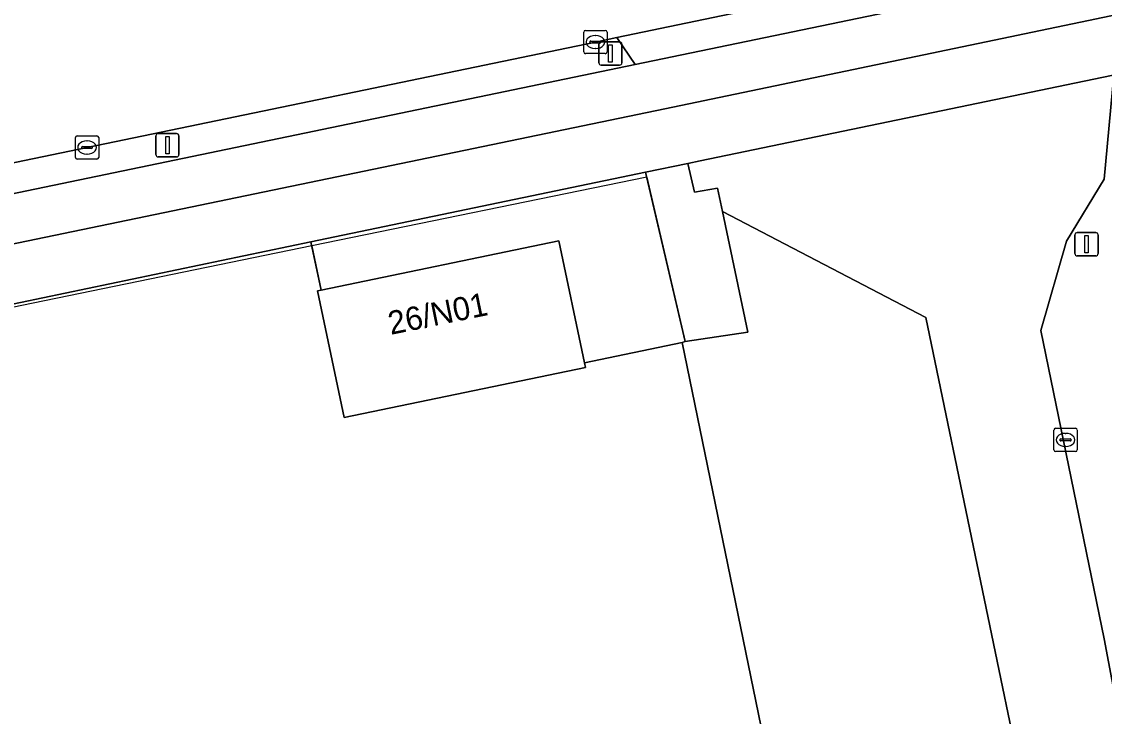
# Model space of a CAD drawing. Extents: x 164494 to 166241, y 382475 to 384495.
# Drawn here: x 164884.73 to 164931.19, y 384302.19 to 384331.99 of the extents above; entities that cross this region are included whole.
import ezdxf

# ---------------------------------------------------------------- set-up
doc = ezdxf.new("R2010")
doc.units = 0
for name, color, linetype in [('IMGEO_Berm_groen', 7, 'Continuous'), ('IMGEO_Erf', 7, 'Continuous'), ('IMGEO_Fietspad_open', 7, 'Continuous'), ('IMGEO_Groenvoorziening', 7, 'Continuous'), ('IMGEO_Hek', 7, 'Continuous'), ('IMGEO_Kolk', 7, 'Continuous'), ('IMGEO_Lichtmast', 7, 'Continuous'), ('IMGEO_Pand', 7, 'Continuous'), ('IMGEO_Pand_nummerreeks', 7, 'Continuous'), ('IMGEO_Rijbaan_lokaal_open', 7, 'Continuous'), ('IMGEO_Voetpad_open', 7, 'Continuous')]:
    doc.layers.add(name, color=color, linetype=linetype)

msp = doc.modelspace()

# ---------------------------------------------------------------- linework, layer by layer
at = {"layer": 'IMGEO_Berm_groen'}
msp.add_lwpolyline([(164911.059, 384330.145), (164910.275, 384331.309), (164909.353, 384331.116), (164887.539, 384326.59), (164866.083, 384322.138), (164847.04, 384318.189), (164832.428, 384315.154), (164832.678, 384313.85), (164868.55, 384321.331)], close=True, dxfattribs=at)
at = {"layer": 'IMGEO_Erf'}
msp.add_lwpolyline([(164931.595, 384329.704), (164931.189, 384325.235), (164929.571, 384322.569), (164928.461, 384318.744), (164931.192, 384305.516), (164935.029, 384285.096), (164930.87, 384284.21), (164924.878, 384283.015), (164922.096, 384296.28), (164917.769, 384295.38), (164913.081, 384318.227), (164908.88, 384317.354), (164908.923, 384317.148), (164898.571, 384315.011), (164897.432, 384320.445), (164897.584, 384320.476), (164897.149, 384322.536), (164869.34, 384316.739), (164837.573, 384310.195), (164815.303, 384305.586), (164810.439, 384304.577), (164802.345, 384302.907), (164801.347, 384302.69), (164878.385, 384108.38)], dxfattribs=at)
at = {"layer": 'IMGEO_Fietspad_open'}
for points in [[(165118.509, 384373.384), (165114.768, 384372.637), (165100.699, 384369.712), (165051.79, 384359.513), (165001.461, 384348.974), (164996.183, 384347.859), (164980.371, 384344.544), (164956.926, 384339.68), (164933.359, 384334.783), (164911.059, 384330.145), (164868.55, 384321.331), (164832.678, 384313.85), (164825.97, 384312.501), (164814.364, 384310.101), (164814.35, 384310.172), (164809.331, 384309.126), (164809.333, 384309.08), (164801.696, 384307.495)], [(164802.068, 384305.407), (164809.925, 384307.04), (164833.08, 384311.822), (164838.611, 384312.969), (164868.92, 384319.253), (164912.329, 384328.255), (164932.507, 384332.46), (164958.923, 384337.938), (164978.743, 384342.085), (164996.584, 384345.814), (165001.876, 384346.919), (165052.181, 384357.436), (165101.155, 384367.679), (165118.614, 384371.278), (165123.59, 384372.323)]]:
    msp.add_lwpolyline(points, dxfattribs=at)
at = {"layer": 'IMGEO_Groenvoorziening'}
msp.add_lwpolyline([(164930.735, 384284.803), (164925.86, 384283.826), (164923.229, 384296.371), (164928.077, 384297.39), (164923.539, 384319.297), (164914.805, 384323.848), (164915.899, 384318.672), (164913.199, 384318.262), (164913.081, 384318.227), (164917.769, 384295.38), (164922.096, 384296.28), (164924.878, 384283.015), (164930.87, 384284.21)], close=True, dxfattribs=at)
at = {"layer": 'IMGEO_Hek'}
for points in [[(164911.555, 384325.324), (164897.184, 384322.369)], [(164911.555, 384325.324), (164913.199, 384318.262)], [(164897.184, 384322.369), (164884.739, 384319.811), (164842.119, 384310.96), (164840.566, 384310.552)], [(164897.184, 384322.369), (164897.584, 384320.476)], [(164913.081, 384318.227), (164908.88, 384317.354)], [(164913.199, 384318.262), (164913.081, 384318.227)], [(164913.081, 384318.227), (164917.769, 384295.38)]]:
    msp.add_lwpolyline(points, dxfattribs=at)
at = {"layer": 'IMGEO_Kolk'}
for p, q in [((164908.852, 384330.69), (164908.852, 384331.542)), ((164908.927, 384331.616), (164909.779, 384331.616)), ((164909.34, 384331.396), (164909.365, 384331.396)), ((164909.853, 384331.542), (164909.853, 384330.69)), ((164909.111, 384331.11), (164909.111, 384331.122)), ((164909.549, 384331.073), (164909.151, 384331.073)), ((164909.154, 384331.159), (164909.552, 384331.159)), ((164909.595, 384331.122), (164909.595, 384331.11)), ((164909.779, 384330.616), (164908.927, 384330.616)), ((164909.363, 384330.836), (164909.338, 384330.836)), ((164887.038, 384326.164), (164887.038, 384327.016)), ((164887.113, 384327.09), (164887.965, 384327.09)), ((164887.526, 384326.87), (164887.551, 384326.87)), ((164888.039, 384327.016), (164888.039, 384326.164)), ((164887.297, 384326.584), (164887.297, 384326.596)), ((164887.735, 384326.547), (164887.337, 384326.547)), ((164887.34, 384326.633), (164887.738, 384326.633)), ((164887.549, 384326.31), (164887.524, 384326.31)), ((164887.781, 384326.596), (164887.781, 384326.584)), ((164887.965, 384326.09), (164887.113, 384326.09)), ((164929.029, 384313.618), (164929.029, 384314.47)), ((164929.104, 384314.544), (164929.956, 384314.544)), ((164929.517, 384314.324), (164929.542, 384314.324)), ((164930.03, 384314.47), (164930.03, 384313.618)), ((164929.288, 384314.038), (164929.288, 384314.05)), ((164929.726, 384314.001), (164929.328, 384314.001)), ((164929.331, 384314.087), (164929.729, 384314.087)), ((164929.54, 384313.764), (164929.515, 384313.764)), ((164929.772, 384314.05), (164929.772, 384314.038)), ((164929.956, 384313.544), (164929.104, 384313.544))]:
    msp.add_line(p, q, dxfattribs=at)
for points in [[(164908.852, 384330.69), (164908.852, 384331.542)], [(164908.927, 384331.616), (164909.779, 384331.616)], [(164909.853, 384331.542), (164909.853, 384330.69)], [(164909.779, 384330.616), (164908.927, 384330.616)], [(164887.038, 384326.164), (164887.038, 384327.016)], [(164887.113, 384327.09), (164887.965, 384327.09)], [(164888.039, 384327.016), (164888.039, 384326.164)], [(164887.965, 384326.09), (164887.113, 384326.09)], [(164929.029, 384313.618), (164929.029, 384314.47)], [(164929.104, 384314.544), (164929.956, 384314.544)], [(164930.03, 384314.47), (164930.03, 384313.618)], [(164929.956, 384313.544), (164929.104, 384313.544)]]:
    msp.add_lwpolyline(points, dxfattribs=at)
for centre, radius, start, end in [((164908.929, 384331.54), 0.0765, 91.552, 178.448), ((164908.929, 384331.54), 0.0765, 91.552, 178.448), ((164909.777, 384331.54), 0.0765, 1.552, 88.448), ((164909.777, 384331.54), 0.0765, 1.552, 88.448), ((164909.151, 384331.119), 0.0403, 85.8775, 175.7526), ((164909.148, 384331.109), 0.0366, 178.938, 274.7102), ((164909.552, 384331.116), 0.043, 264.8664, 352.4533), ((164909.556, 384331.121), 0.0386, 1.7309, 96.639), ((164908.929, 384330.692), 0.0765, 181.552, 268.448), ((164908.929, 384330.692), 0.0765, 181.552, 268.448), ((164909.777, 384330.692), 0.0765, 271.552, 358.448), ((164909.777, 384330.692), 0.0765, 271.552, 358.448), ((164887.115, 384327.014), 0.0765, 91.552, 178.448), ((164887.115, 384327.014), 0.0765, 91.552, 178.448), ((164887.963, 384327.014), 0.0765, 1.552, 88.448), ((164887.963, 384327.014), 0.0765, 1.552, 88.448), ((164887.337, 384326.593), 0.0403, 85.8775, 175.7526), ((164887.334, 384326.583), 0.0366, 178.938, 274.7102), ((164887.738, 384326.59), 0.043, 264.8664, 352.4533), ((164887.742, 384326.595), 0.0386, 1.7309, 96.639), ((164887.115, 384326.166), 0.0765, 181.552, 268.448), ((164887.115, 384326.166), 0.0765, 181.552, 268.448), ((164887.963, 384326.166), 0.0765, 271.552, 358.448), ((164887.963, 384326.166), 0.0765, 271.552, 358.448), ((164929.106, 384314.468), 0.0765, 91.552, 178.448), ((164929.106, 384314.468), 0.0765, 91.552, 178.448), ((164929.954, 384314.468), 0.0765, 1.552, 88.448), ((164929.954, 384314.468), 0.0765, 1.552, 88.448), ((164929.328, 384314.047), 0.0403, 85.8775, 175.7526), ((164929.325, 384314.037), 0.0366, 178.938, 274.7102), ((164929.729, 384314.044), 0.043, 264.8664, 352.4533), ((164929.733, 384314.049), 0.0386, 1.7309, 96.639), ((164929.106, 384313.62), 0.0765, 181.552, 268.448), ((164929.106, 384313.62), 0.0765, 181.552, 268.448), ((164929.954, 384313.62), 0.0765, 271.552, 358.448), ((164929.954, 384313.62), 0.0765, 271.552, 358.448)]:
    msp.add_arc(centre, radius, start, end, dxfattribs=at)
for centre, major_axis, ratio, start_param, end_param in [((164909.339, 384331.116), (-0.387, 0.002), 0.722429, 4.712389, 7.853982), ((164909.364, 384331.116), (-0.39, 0.002), 0.717154, 1.570796, 4.712389), ((164887.525, 384326.59), (-0.387, 0.002), 0.722429, 4.712389, 7.853982), ((164887.55, 384326.59), (-0.39, 0.002), 0.717154, 1.570796, 4.712389), ((164929.516, 384314.044), (-0.387, 0.002), 0.722429, 4.712389, 7.853982), ((164929.541, 384314.044), (-0.39, 0.002), 0.717154, 1.570796, 4.712389)]:
    msp.add_ellipse(centre, major_axis=major_axis, ratio=ratio, start_param=start_param, end_param=end_param, dxfattribs=at)
at = {"layer": 'IMGEO_Lichtmast'}
for p, q in [((164909.503, 384330.224), (164909.503, 384331.024)), ((164909.503, 384331.024), (164909.503, 384330.224)), ((164909.603, 384331.124), (164910.393, 384331.124)), ((164910.393, 384331.124), (164909.603, 384331.124)), ((164910.493, 384331.024), (164910.493, 384330.224)), ((164910.493, 384330.224), (164910.493, 384331.024)), ((164910.393, 384330.124), (164909.603, 384330.124)), ((164909.603, 384330.124), (164910.393, 384330.124)), ((164890.595, 384327.187), (164891.385, 384327.187)), ((164891.385, 384327.187), (164890.595, 384327.187)), ((164890.495, 384326.287), (164890.495, 384327.087)), ((164890.495, 384327.087), (164890.495, 384326.287)), ((164891.485, 384327.087), (164891.485, 384326.287)), ((164891.485, 384326.287), (164891.485, 384327.087)), ((164891.385, 384326.187), (164890.595, 384326.187)), ((164890.595, 384326.187), (164891.385, 384326.187)), ((164929.933, 384322.04), (164929.933, 384322.84)), ((164929.933, 384322.84), (164929.933, 384322.04)), ((164930.033, 384322.94), (164930.823, 384322.94)), ((164930.823, 384322.94), (164930.033, 384322.94)), ((164930.923, 384322.84), (164930.923, 384322.04)), ((164930.923, 384322.04), (164930.923, 384322.84)), ((164930.823, 384321.94), (164930.033, 384321.94)), ((164930.033, 384321.94), (164930.823, 384321.94))]:
    msp.add_line(p, q, dxfattribs=at)
for points in [[(164909.923, 384330.999), (164910.073, 384330.999), (164910.073, 384330.249), (164909.923, 384330.249), (164909.923, 384330.999)], [(164890.915, 384327.062), (164891.065, 384327.062), (164891.065, 384326.312), (164890.915, 384326.312), (164890.915, 384327.062)], [(164930.353, 384322.815), (164930.503, 384322.815), (164930.503, 384322.065), (164930.353, 384322.065), (164930.353, 384322.815)]]:
    msp.add_lwpolyline(points, dxfattribs=at)
for centre, start, end in [((164909.603, 384331.024), 90, 180), ((164909.603, 384331.024), 90, 180), ((164910.393, 384331.024), 0, 90), ((164910.393, 384331.024), 360, 90), ((164909.603, 384330.224), 180, 270), ((164909.603, 384330.224), 180, 270), ((164910.393, 384330.224), 270, 0), ((164910.393, 384330.224), 270, 0), ((164890.595, 384327.087), 90, 180), ((164890.595, 384327.087), 90, 180), ((164891.385, 384327.087), 0, 90), ((164891.385, 384327.087), 360, 90), ((164890.595, 384326.287), 180, 270), ((164890.595, 384326.287), 180, 270), ((164891.385, 384326.287), 270, 0), ((164891.385, 384326.287), 270, 0), ((164930.033, 384322.84), 90, 180), ((164930.033, 384322.84), 90, 180), ((164930.823, 384322.84), 0, 90), ((164930.823, 384322.84), 360, 90), ((164930.033, 384322.04), 180, 270), ((164930.033, 384322.04), 180, 270), ((164930.823, 384322.04), 270, 0), ((164930.823, 384322.04), 270, 0)]:
    msp.add_arc(centre, 0.1, start, end, dxfattribs=at)
at = {"layer": 'IMGEO_Pand'}
msp.add_lwpolyline([(164907.784, 384322.582), (164897.584, 384320.476), (164897.432, 384320.445), (164898.571, 384315.011), (164908.923, 384317.148), (164908.88, 384317.354)], close=True, dxfattribs=at)
at = {"layer": 'IMGEO_Rijbaan_lokaal_open'}
msp.add_lwpolyline([(164799.153, 384308.224), (164802.045, 384308.824), (164809.079, 384310.283), (164814.127, 384311.33), (164814.848, 384311.48), (164825.542, 384313.724), (164825.715, 384313.76), (164832.428, 384315.154), (164847.04, 384318.189), (164866.083, 384322.138), (164887.539, 384326.59), (164909.353, 384331.116), (164910.275, 384331.309), (164923.017, 384333.971), (164933.937, 384336.234)], dxfattribs=at)
for points in [[(164933.359, 384334.783), (164933.937, 384336.234), (164923.017, 384333.971), (164910.275, 384331.309), (164911.059, 384330.145)], [(164928.461, 384318.744), (164929.571, 384322.569), (164931.189, 384325.235), (164931.595, 384329.704), (164931.494, 384329.683), (164913.849, 384326.017), (164913.321, 384325.907), (164913.602, 384324.675), (164914.593, 384324.849), (164914.805, 384323.848), (164923.539, 384319.297), (164928.077, 384297.39), (164930.735, 384284.803), (164930.87, 384284.21), (164935.029, 384285.096), (164931.192, 384305.516)]]:
    msp.add_lwpolyline(points, close=True, dxfattribs=at)
at = {"layer": 'IMGEO_Voetpad_open'}
for points in [[(165123.59, 384372.323), (165118.614, 384371.278), (165101.155, 384367.679), (165052.181, 384357.436), (165001.876, 384346.919), (164996.584, 384345.814), (164978.743, 384342.085), (164958.923, 384337.938), (164932.507, 384332.46), (164912.329, 384328.255), (164868.92, 384319.253), (164838.611, 384312.969), (164833.08, 384311.822), (164809.925, 384307.04), (164802.068, 384305.407)], [(164801.347, 384302.69), (164802.345, 384302.907), (164810.439, 384304.577), (164815.303, 384305.586), (164837.573, 384310.195), (164869.34, 384316.739), (164897.149, 384322.536), (164911.507, 384325.529), (164913.321, 384325.907), (164913.849, 384326.017), (164931.494, 384329.683)]]:
    msp.add_lwpolyline(points, dxfattribs=at)
for points in [[(164914.805, 384323.848), (164914.593, 384324.849), (164913.602, 384324.675), (164913.321, 384325.907), (164911.507, 384325.529), (164913.199, 384318.262), (164915.899, 384318.672)], [(164907.784, 384322.582), (164908.88, 384317.354), (164913.081, 384318.227), (164913.199, 384318.262), (164911.507, 384325.529), (164897.149, 384322.536), (164897.584, 384320.476)]]:
    msp.add_lwpolyline(points, close=True, dxfattribs=at)

# ---------------------------------------------------------------- texts
at = {"layer": 'IMGEO_Pand_nummerreeks'}
msp.add_text('26/N01', height=1, rotation=11.4706, dxfattribs=at).set_placement((164900.569, 384318.55))

doc.saveas('drawing.dxf')
